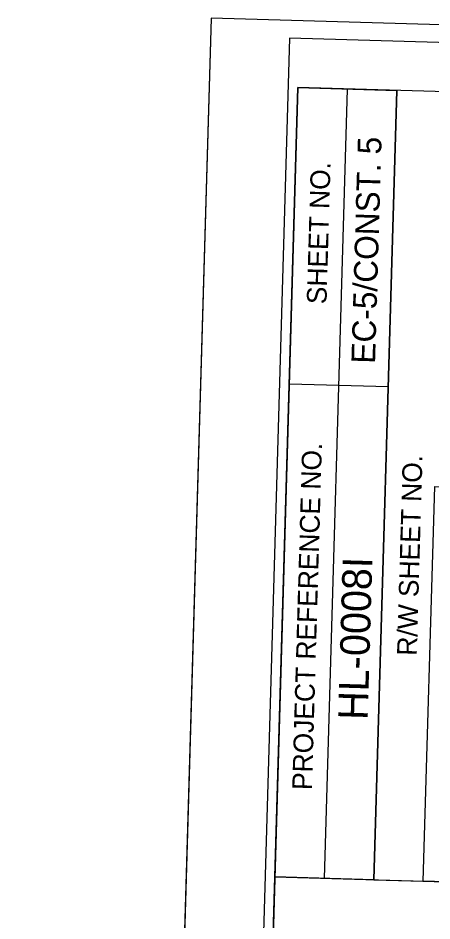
# Model space of a CAD drawing. Extents: x 2096987 to 2098161, y 681809 to 686842.
# Drawn here: x 2096986.8 to 2097091.7, y 686613.6 to 686842.4 of the extents above; entities that cross this region are included whole.
import ezdxf

# ---------------------------------------------------------------- set-up
doc = ezdxf.new("R2010")
doc.units = 0
for name, color, linetype in [('Sheet Block Title CELL', 7, 'Continuous'), ('Sheet Data Field CELL', 7, 'Continuous'), ('Sheet Plan And Profile CELL', 7, 'Continuous'), ('Sheet Plot Border Inside CELL', 7, 'Continuous'), ('Sheet Sticker Exception Certification CELL', 7, 'Continuous'), ('Sheet Sticker Incomplete CELL', 7, 'Continuous')]:
    doc.layers.add(name, color=color, linetype=linetype)

msp = doc.modelspace()

# ---------------------------------------------------------------- linework, layer by layer
at = {"layer": 'Sheet Block Title CELL'}
msp.add_lwpolyline([(2098081.34, 685127.82), (2098130.26, 686810.61), (2097035.73, 686842.43), (2096986.81, 685159.64)], close=True, dxfattribs=at)
at = {"layer": 'Sheet Data Field CELL'}
msp.add_lwpolyline([(2098061.73, 685141.4), (2098110.13, 686806.68), (2097055.59, 686837.35), (2097007.18, 685172.06)], close=True, dxfattribs=at)
at = {"layer": 'Sheet Plan And Profile CELL'}
msp.add_line((2097035.73, 686842.43), (2096986.81, 685159.64), dxfattribs=at)
at = {"layer": 'Sheet Plot Border Inside CELL'}
msp.add_lwpolyline([(2098075.38, 685697.44), (2097236.74, 685318.87), (2097014.12, 685325.38), (2097045.97, 686421.2), (2097047.21, 686463.77), (2097051.88, 686624.82), (2097288.1, 686617.97), (2097291.39, 686731.15), (2098104.74, 686707.51)], close=True, dxfattribs=at)
msp.add_lwpolyline([(2098075.38, 685697.44), (2097236.74, 685318.87), (2097014.12, 685325.38), (2097045.97, 686421.2), (2097047.21, 686463.77), (2097051.88, 686624.82), (2097288.1, 686617.97), (2097291.39, 686731.15), (2098104.74, 686707.51)], close=True, dxfattribs=at)
at = {"layer": 'Sheet Sticker Exception Certification CELL'}
for p, q in [((2097064.43, 686624.44), (2097070.25, 686824.41)), ((2097076.96, 686624.09), (2097082.75, 686824.05)), ((2097076.96, 686624.09), (2097082.75, 686824.05)), ((2097055.59, 686749.78), (2097080.58, 686749.1)), ((2097076.96, 686624.09), (2097089.44, 686623.73))]:
    msp.add_line(p, q, dxfattribs=at)
for points in [[(2097057.71, 686824.81), (2097014.12, 685325.41), (2098063.68, 685294.9), (2098107.27, 686794.27)], [(2097051.88, 686624.82), (2097057.71, 686824.81), (2097082.75, 686824.05), (2097076.96, 686624.09)], [(2098063.68, 685294.9), (2097014.15, 685325.38), (2097051.88, 686624.82), (2097201.88, 686620.47), (2097207.71, 686820.43), (2098107.27, 686794.27)], [(2097089.44, 686623.73), (2097092.35, 686723.74), (2097204.82, 686720.47), (2097201.88, 686620.47)]]:
    msp.add_lwpolyline(points, close=True, dxfattribs=at)

# ---------------------------------------------------------------- texts
for s, height, p in [('SHEET NO.', 5, (2097064.94, 686769.87)), ('PROJECT REFERENCE NO.', 5.0001, (2097061.25, 686646.76)), ('R/W SHEET NO.', 5.0001, (2097087.8, 686680.8))]:
    msp.add_text(s, height=height, rotation=88.3348, dxfattribs=at).set_placement(p)
at = {"layer": 'Sheet Sticker Incomplete CELL'}
for s, height, p in [('EC-5/CONST. 5', 6, (2097077.24, 686754.79)), ('HL-0008I', 7.5, (2097075.37, 686664.51))]:
    msp.add_text(s, height=height, rotation=88.3348, dxfattribs=at).set_placement(p)

doc.saveas('drawing.dxf')
